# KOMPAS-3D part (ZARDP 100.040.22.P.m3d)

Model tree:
1. Операция без истории:1
2. Операция без истории:2
3. Операция без истории:3
4. Операция без истории:4
5. Операция без истории:5
6. Операция без истории:6
7. Операция без истории:7
8. Операция без истории:8
9. Операция без истории:9
10. Операция без истории:10
11. Операция без истории:11
12. Операция без истории:12
13. Операция без истории:13
14. Операция без истории:14
15. Операция без истории:15
16. Операция без истории:16
17. Операция без истории:17
18. Операция без истории:18
19. Операция без истории:19
20. Операция без истории:20
21. Операция без истории:21
22. Операция без истории:22
23. Операция без истории:23
24. Операция без истории:24
25. Операция без истории:25
26. Операция без истории:26
27. Операция без истории:27
28. Операция без истории:28
29. Операция без истории:29
30. Операция без истории:30
31. Операция без истории:31
32. Операция без истории:32
33. Операция без истории:33
34. Операция без истории:34
35. Операция без истории:35
36. Операция без истории:36
37. Операция без истории:37
38. Операция без истории:38
39. Операция без истории:39
40. Операция без истории:40
41. Операция без истории:41
42. Операция без истории:42
43. Операция без истории:43
44. Операция без истории:44
45. Операция без истории:45
46. Операция без истории:46
47. Операция без истории:47
48. Операция без истории:48
49. Операция без истории:49
50. Операция без истории:50
51. Операция без истории:51
52. Операция без истории:52
53. Операция без истории:53
54. Операция без истории:54
55. Операция без истории:55
56. Операция без истории:56
57. Операция без истории:57
58. Операция без истории:58
59. Операция без истории:59
60. Операция без истории:60
61. Операция без истории:61
62. Операция без истории:62
63. Операция без истории:63

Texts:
  ЗАРДП.100.040.22-Р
